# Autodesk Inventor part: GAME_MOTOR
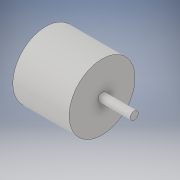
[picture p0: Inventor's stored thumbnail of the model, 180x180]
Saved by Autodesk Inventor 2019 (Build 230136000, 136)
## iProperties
Created: 2020-02
Part Number: GAME_MOTOR
Material: Generic
Document SubType Name: Modeling
Designer: Siddharth
Density: 1 g/cm^3
Appearance: Default
Author: Siddharth
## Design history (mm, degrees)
sketch "Sketch1"
  geometry: L1 (-60.746, 0)-(55.512, 0); L2 (0, 0)-(35, 0); L3 (35, 0)-(35, 20.5); L4 (35, 20.5)-(0, 20.5); L5 (0, 20.5)-(0, 0); L6 (35, 0)-(55, 0); L7 (55, 0)-(55, 2.5); L8 (55, 2.5)-(35, 2.5); L9 (35, 2.5)-(35, 0)
  constraints: 18 end point, 4 parallel, 3 horizontal, 2 perpendicular
  dimensions: "d0" = 35 distance of L4.end L3.end; "d1" = 20.5 distance of L3.end L2.end; "d2" = 20 distance of L8.end L7.end; "d3" = 2.5 distance of L7.end L6.end
revolve "Revolution1" sketch "Sketch1" stored, may be unused: angle "d4" = 90 deg
body "Solid1"
